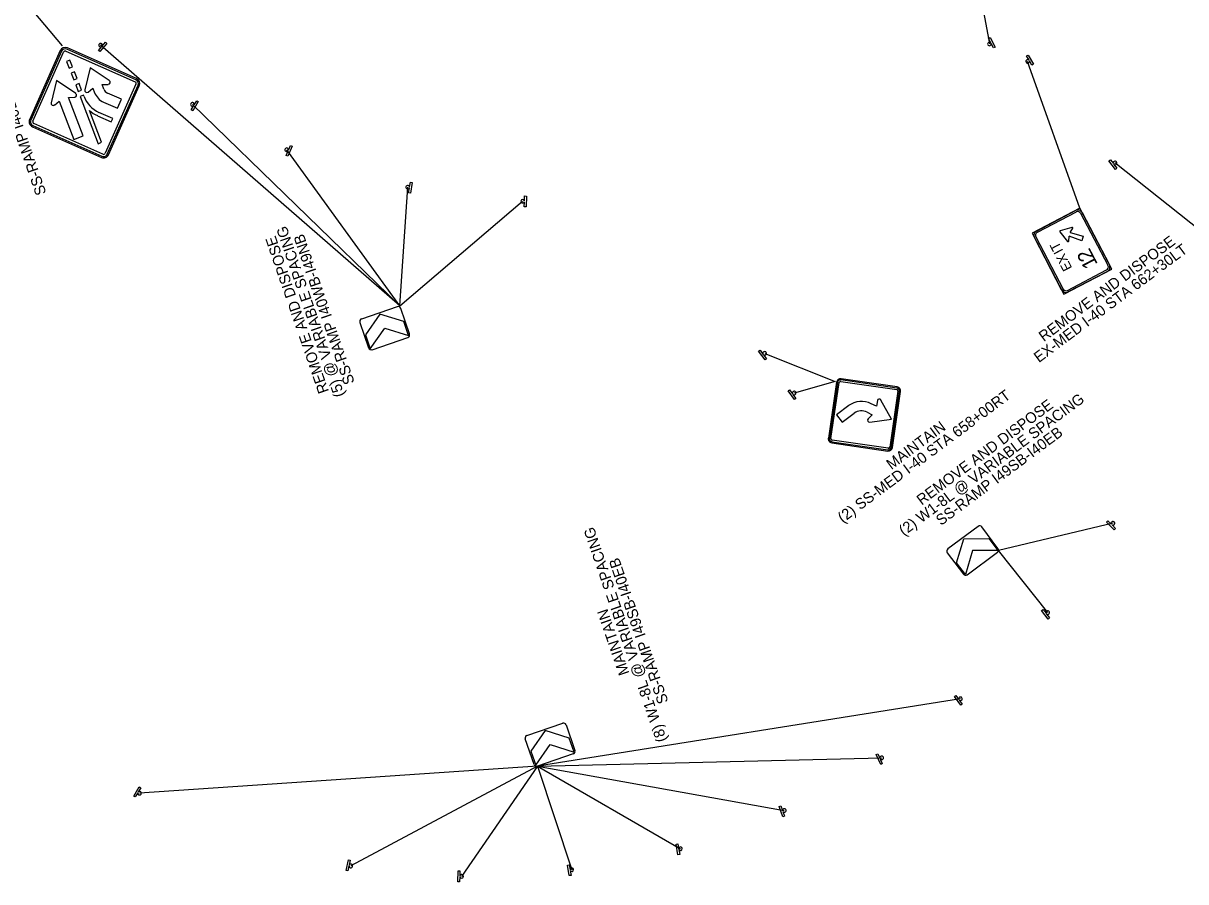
# Model space of a CAD drawing. Extents: x 641128 to 649424, y 422807 to 432853.
# Drawn here: x 644900 to 646193, y 425986 to 426941 of the extents above; entities that cross this region are included whole.
import ezdxf

# ---------------------------------------------------------------- set-up
doc = ezdxf.new("R2010")
doc.units = 0
for name, color, linetype in [('R_Anno_Text', 7, 'Continuous'), ('R_Dimension_2', 7, 'Continuous'), ('S_SIGN', 7, 'Continuous')]:
    doc.layers.add(name, color=color, linetype=linetype)

msp = doc.modelspace()

# ---------------------------------------------------------------- linework, layer by layer
at = {"layer": 'S_SIGN'}
for p, q in [((645890, 427374.3), (645974.6, 426917.5)), ((644944, 426915.5), (644741.6, 427157.1)), ((644988.1, 426915.2), (644991.7, 426919.4)), ((644991.7, 426919.4), (644993.2, 426918.1)), ((645973.6, 426923.7), (645975.4, 426924.6)), ((645976.2, 426918.8), (645973.6, 426923.7)), ((645975.4, 426924.6), (645981, 426914)), ((644941.5, 426910.1), (644907.4, 426833.3)), ((645026.2, 426879), (644949.4, 426913.1)), ((644983.8, 426910.3), (644987.5, 426914.5)), ((644985.3, 426909), (644983.8, 426910.3)), ((644993.2, 426918.1), (644985.3, 426909)), ((645319, 426626.2), (644986.3, 426916.2)), ((644987.5, 426914.5), (644987.4, 426914.6)), ((644988, 426915.3), (644988.1, 426915.2)), ((645976.1, 426918.8), (645976.2, 426918.8)), ((645979.2, 426913.1), (645976.6, 426918)), ((645976.6, 426918), (645976.6, 426918)), ((645981, 426914), (645979.2, 426913.1)), ((646015.8, 426904.2), (646017.5, 426905.2)), ((646018.6, 426899.4), (646015.8, 426904.2)), ((646075.2, 426734.7), (646017.1, 426898)), ((646017.5, 426905.2), (646023.7, 426894.9)), ((646018.6, 426899.4), (646018.6, 426899.4)), ((646019.1, 426898.6), (646019, 426898.6)), ((646021.9, 426893.9), (646019.1, 426898.6)), ((646023.7, 426894.9), (646021.9, 426893.9)), ((644974.8, 426891.1), (644968.7, 426866.3)), ((644995.9, 426876.8), (644974.8, 426891.1)), ((644937.4, 426876.7), (644931.3, 426851.9)), ((644958.6, 426862.4), (644937.4, 426876.7)), ((644972.3, 426864), (644977.6, 426868.3)), ((644977.6, 426868.3), (644979.6, 426863.3)), ((644987.9, 426872.3), (644994.8, 426872.6)), ((644989.8, 426867.3), (644987.9, 426872.3)), ((644995.1, 426794.3), (645029.2, 426871)), ((644950.6, 426857.9), (644957.5, 426858.3)), ((644967, 426815.2), (644950.6, 426857.9)), ((644967.3, 426860.4), (644963.6, 426858.9)), ((644963.6, 426858.9), (644983.7, 426806.6)), ((644967.9, 426858.9), (644967.3, 426860.4)), ((645009.4, 426856), (644994, 426862.8)), ((645004.9, 426846), (645009.4, 426856)), ((645090.4, 426849.7), (645093.2, 426854.4)), ((645093.2, 426854.4), (645094.9, 426853.4)), ((644934.9, 426849.6), (644940.3, 426854)), ((644940.3, 426854), (644956.7, 426811.3)), ((644987.4, 426808.1), (644973.8, 426843.6)), ((644999.8, 426834.6), (644984.5, 426841.4)), ((644989.6, 426852.8), (645004.9, 426846)), ((645087, 426844.1), (645089.9, 426848.9)), ((645088.7, 426843.1), (645087, 426844.1)), ((645319, 426626.2), (645088.4, 426850.3)), ((645094.9, 426853.4), (645088.7, 426843.1)), ((645089.9, 426848.9), (645089.9, 426848.9)), ((645090.3, 426849.7), (645090.4, 426849.7)), ((644982.9, 426837.7), (644998.2, 426830.9)), ((644998.2, 426830.9), (644999.8, 426834.6)), ((644910.4, 426825.4), (644987.2, 426791.2)), ((644956.7, 426811.3), (644967, 426815.2)), ((644983.7, 426806.6), (644987.4, 426808.1)), ((645199.2, 426803.8), (645194.5, 426792.7)), ((645195.2, 426799.5), (645197.3, 426804.6)), ((645197.3, 426804.6), (645199.2, 426803.8)), ((645192.7, 426793.5), (645194.8, 426798.6)), ((645194.5, 426792.7), (645192.7, 426793.5)), ((645319, 426626.2), (645193.2, 426799.8)), ((645194.8, 426798.6), (645194.8, 426798.7)), ((645195.1, 426799.5), (645195.2, 426799.5)), ((646107.5, 426787.6), (646109.1, 426788.8)), ((646114.6, 426778), (646107.5, 426787.6)), ((646109.1, 426788.8), (646112.4, 426784.4)), ((646112.4, 426784.4), (646112.4, 426784.4)), ((646113, 426783.7), (646112.9, 426783.6)), ((646112.9, 426783.6), (646116.2, 426779.2)), ((646343.9, 426602.6), (646114.2, 426785.2)), ((646116.2, 426779.2), (646114.6, 426778)), ((645329.9, 426758.3), (645330.9, 426763.8)), ((645330.9, 426763.8), (645332.8, 426763.4)), ((645319, 426626.2), (645327.8, 426758.2)), ((645328.7, 426752), (645329.7, 426757.4)), ((645330.7, 426751.6), (645328.7, 426752)), ((645329.7, 426757.4), (645329.7, 426757.5)), ((645329.8, 426758.3), (645329.9, 426758.3)), ((645332.8, 426763.4), (645330.7, 426751.6)), ((645319, 426626.2), (645455.5, 426742.6)), ((645457.3, 426736.5), (645457.5, 426742)), ((645457.5, 426742.9), (645457.8, 426748.5)), ((645457.5, 426742.9), (645457.5, 426742.9)), ((645457.5, 426742), (645457.5, 426742)), ((645457.8, 426748.5), (645459.8, 426748.4)), ((645459.8, 426748.4), (645459.3, 426736.4)), ((645459.3, 426736.4), (645457.3, 426736.5)), ((645316.2, 426625.2), (645276.5, 426611.6)), ((645329.7, 426595), (645320, 426623.4)), ((645296.8, 426617), (645280.9, 426594.1)), ((645323.4, 426608.7), (645296.8, 426617)), ((645274.6, 426607.8), (645284.3, 426579.4)), ((645286.2, 426578.5), (645302.2, 426601.4)), ((645302.2, 426601.4), (645328.8, 426593.1)), ((645288.2, 426577.5), (645327.9, 426591.2)), ((645717.9, 426575.7), (645719.5, 426576.9)), ((645725.1, 426566.1), (645717.9, 426575.7)), ((645719.5, 426576.9), (645722.8, 426572.4)), ((645722.8, 426572.4), (645722.9, 426572.4)), ((645723.4, 426571.7), (645723.4, 426571.7)), ((645723.4, 426571.7), (645726.7, 426567.3)), ((645726.7, 426567.3), (645725.1, 426566.1)), ((645872, 426536), (645809.7, 426545.1)), ((645750.7, 426531.7), (645752.3, 426532.9)), ((645757.8, 426522.1), (645750.7, 426531.7)), ((645752.3, 426532.9), (645755.6, 426528.5)), ((645804.6, 426541.3), (645795.5, 426479)), ((645755.6, 426528.5), (645755.6, 426528.5)), ((645756.2, 426527.8), (645756.1, 426527.7)), ((645756.1, 426527.7), (645759.4, 426523.3)), ((645759.4, 426523.3), (645757.8, 426522.1)), ((645850, 426520.8), (645849, 426514.5)), ((645865.7, 426500.2), (645854, 426521.5)), ((645866.7, 426468.6), (645875.8, 426530.9)), ((645818.1, 426515.3), (645804.6, 426505.2)), ((645810.9, 426496.8), (645824.3, 426506.8)), ((645838.5, 426508.1), (645844.3, 426505.1)), ((645849, 426514.5), (645843.2, 426517.4)), ((645804.6, 426505.2), (645810.9, 426496.8)), ((645844.3, 426505.1), (645839.8, 426500.6)), ((645841.6, 426497), (645865.7, 426500.2)), ((645799.3, 426473.9), (645861.6, 426464.8)), ((645962, 426381), (645928.3, 426355.9)), ((645984.1, 426356.4), (645966.2, 426380.4)), ((646112, 426384.4), (645984.7, 426354)), ((646104.9, 426385.8), (646106.4, 426387.2)), ((646113.4, 426377.3), (646104.9, 426385.8)), ((646106.4, 426387.2), (646110.3, 426383.3)), ((646110.3, 426383.3), (646110.3, 426383.3)), ((646111, 426382.7), (646110.9, 426382.6)), ((646110.9, 426382.6), (646114.8, 426378.7)), ((646114.8, 426378.7), (646113.4, 426377.3)), ((645937.9, 426340.6), (645946.1, 426367.3)), ((645946.1, 426367.3), (645974, 426367.5)), ((645927.7, 426351.7), (645945.7, 426327.7)), ((645955.9, 426354.1), (645947.8, 426327.4)), ((645949.8, 426327.1), (645983.5, 426352.2)), ((645983.8, 426354.3), (645955.9, 426354.1)), ((646039.4, 426285.1), (645984.7, 426354)), ((646032.6, 426287.5), (646034.2, 426288.7)), ((646039.9, 426277.9), (646032.6, 426287.5)), ((646034.2, 426288.7), (646037.6, 426284.3)), ((646037.6, 426284.3), (646037.6, 426284.3)), ((646038.2, 426283.6), (646038.1, 426283.5)), ((646038.1, 426283.5), (646041.5, 426279.1)), ((646041.5, 426279.1), (646039.9, 426277.9)), ((645942.4, 426189.2), (645472, 426114.3)), ((645935.6, 426191.6), (645937.2, 426192.8)), ((645942.8, 426182), (645935.6, 426191.6)), ((645937.2, 426192.8), (645940.5, 426188.3)), ((645940.5, 426188.3), (645940.6, 426188.4)), ((645941.1, 426187.6), (645941.1, 426187.6)), ((645941.1, 426187.6), (645944.4, 426183.2)), ((645944.4, 426183.2), (645942.8, 426182)), ((645460.3, 426148.4), (645500.1, 426162)), ((645503.9, 426160.2), (645513.6, 426131.8)), ((645468.2, 426116.2), (645458.5, 426144.6)), ((645480.7, 426153.8), (645464.8, 426130.9)), ((645507.3, 426145.5), (645480.7, 426153.8)), ((645470.1, 426115.3), (645486, 426138.2)), ((645486, 426138.2), (645512.7, 426129.9)), ((645511.8, 426128), (645472, 426114.3)), ((645472, 426114.3), (645854.8, 426123.5)), ((645848.7, 426127.3), (645850.5, 426128.1)), ((645853.7, 426116.3), (645848.7, 426127.3)), ((645850.5, 426128.1), (645852.8, 426123)), ((645852.8, 426123), (645852.9, 426123)), ((645853.3, 426122.2), (645853.2, 426122.2)), ((645853.2, 426122.2), (645855.5, 426117.2)), ((645472, 426114.3), (645029.6, 426084.2)), ((645472, 426114.3), (645264.5, 426003.3)), ((645472, 426114.3), (645387.7, 425991.7)), ((645472, 426114.3), (645510.3, 425999.1)), ((645472, 426114.3), (645631.1, 426022.4)), ((645472, 426114.3), (645746.5, 426065)), ((645855.5, 426117.2), (645853.7, 426116.3)), ((645023.1, 426081.1), (645029.3, 426091.4)), ((645024.8, 426080), (645023.1, 426081.1)), ((645027.6, 426084.8), (645024.8, 426080)), ((645027.7, 426084.8), (645027.6, 426084.8)), ((645031, 426090.3), (645028.1, 426085.6)), ((645028.1, 426085.6), (645028.1, 426085.5)), ((645029.3, 426091.4), (645031, 426090.3)), ((645740.8, 426069.4), (645742.7, 426070.1)), ((645744.7, 426058), (645740.8, 426069.4)), ((645742.7, 426070.1), (645744.5, 426064.8)), ((645744.5, 426064.8), (645744.6, 426064.8)), ((645746.6, 426058.7), (645744.7, 426058)), ((645744.9, 426063.9), (645744.8, 426063.9)), ((645744.8, 426063.9), (645746.6, 426058.7)), ((645626.1, 426027.6), (645628.1, 426028)), ((645628.2, 426015.8), (645626.1, 426027.6)), ((645628.1, 426028), (645629, 426022.5)), ((645630.2, 426016.2), (645628.2, 426015.8)), ((645629, 426022.5), (645629.1, 426022.5)), ((645629.3, 426021.6), (645629.2, 426021.6)), ((645629.2, 426021.6), (645630.2, 426016.2)), ((645259.3, 425998.3), (645261.9, 426010)), ((645262.4, 426003.3), (645261.2, 425997.9)), ((645261.9, 426010), (645263.9, 426009.6)), ((645262.5, 426003.3), (645262.4, 426003.3)), ((645263.9, 426009.6), (645262.6, 426004.2)), ((645262.6, 426004.2), (645262.7, 426004.2)), ((645505.3, 426004.3), (645507.3, 426004.6)), ((645507.4, 425992.5), (645505.3, 426004.3)), ((645507.3, 426004.6), (645508.3, 425999.1)), ((645261.2, 425997.9), (645259.3, 425998.3)), ((645383.5, 425985.8), (645383.8, 425997.8)), ((645383.8, 425997.8), (645385.8, 425997.7)), ((645385.6, 425991.2), (645385.5, 425985.7)), ((645385.7, 425991.2), (645385.6, 425991.2)), ((645385.8, 425997.7), (645385.7, 425992.2)), ((645385.7, 425992.2), (645385.7, 425992.1)), ((645509.4, 425992.8), (645507.4, 425992.5)), ((645508.3, 425999.1), (645508.3, 425999.1)), ((645508.5, 425998.3), (645508.4, 425998.2)), ((645508.4, 425998.2), (645509.4, 425992.8)), ((645385.5, 425985.7), (645383.5, 425985.8))]:
    msp.add_line(p, q, dxfattribs=at)
for points in [[(644942.9, 426909.4), (644908.8, 426832.7)], [(644911, 426831.7), (644945.2, 426908.4)], [(644942.9, 426909.4), (644942.9, 426909.4), (644942.9, 426909.4)], [(644947.8, 426909.4), (645024.6, 426875.3)], [(645025.6, 426877.6), (644948.8, 426911.7)], [(644952.2, 426899.6), (644948.5, 426898.1), (644951.4, 426890.7), (644955.1, 426892.1), (644952.2, 426899.6)], [(644957.3, 426886.5), (644953.5, 426885.1), (644956.4, 426877.6), (644960.1, 426879), (644957.3, 426886.5)], [(644962.3, 426873.4), (644958.6, 426872), (644961.4, 426864.5), (644965.2, 426866), (644962.3, 426873.4)], [(645025.6, 426872.7), (644991.4, 426795.9)], [(644993.7, 426794.9), (645027.9, 426871.7)], [(645025.6, 426877.6), (645025.6, 426877.6), (645025.6, 426877.6)], [(644988.8, 426794.9), (644912.1, 426829)], [(644911, 426826.8), (644987.8, 426792.6)], [(644911, 426826.8), (644911, 426826.8), (644911, 426826.8)], [(644993.7, 426794.9), (644993.7, 426794.9), (644993.7, 426794.9)], [(646110.6, 426667.1), (646075.2, 426734.7), (646022, 426706.9), (646057.5, 426639.2), (646110.6, 426667.1), (646110.6, 426667.1), (646110.6, 426667.1)], [(646026.9, 426709.4), (646070.4, 426732.2)], [(646071.2, 426730.6), (646027.7, 426707.8)], [(646071.2, 426730.6), (646071.2, 426730.6), (646071.2, 426730.6)], [(646106.5, 426671.1), (646076.1, 426729.1)], [(646077.7, 426729.9), (646108.1, 426671.9)], [(646066.4, 426713.5), (646053.3, 426709.7)], [(646064.3, 426707.8), (646067.2, 426712.5)], [(646054.9, 426644.1), (646024.6, 426702.1)], [(646026.2, 426702.9), (646056.5, 426644.9)], [(646026.2, 426702.9), (646026.2, 426702.9), (646026.2, 426702.9)], [(646053, 426708.6), (646061.5, 426697.9)], [(646053.5, 426709), (646053.5, 426709), (646053.5, 426709)], [(646062.7, 426698.3), (646063.1, 426703.9)], [(646079, 426703.9), (646077.4, 426698.7), (646063.1, 426703.9)], [(646064.3, 426707.8), (646079, 426703.9), (646079, 426703.9), (646079, 426703.9)], [(646061.4, 426643.4), (646104.9, 426666.2)], [(646105.8, 426664.5), (646062.3, 426641.8)], [(646106.5, 426671.1), (646106.5, 426671.1), (646106.5, 426671.1)], [(646061.4, 426643.4), (646061.4, 426643.4), (646061.4, 426643.4)], [(645280.9, 426594.1), (645286.2, 426578.5), (645302.2, 426601.4), (645328.8, 426593.1), (645323.4, 426608.7), (645296.8, 426617), (645280.9, 426594.1)], [(645724.7, 426573.3), (645803.2, 426542.1), (645757.5, 426529.3)], [(645805.8, 426541.2), (645796.7, 426478.8)], [(645798.4, 426478.6), (645807.6, 426540.9)], [(645805.8, 426541.2), (645805.8, 426541.2), (645805.8, 426541.2)], [(645809.3, 426542.2), (645871.6, 426533.1)], [(645871.8, 426534.8), (645809.5, 426543.9)], [(645872.9, 426531.4), (645863.8, 426469)], [(645865.5, 426468.8), (645874.6, 426531.1)], [(645871.8, 426534.8), (645871.8, 426534.8), (645871.8, 426534.8)], [(645799.5, 426475.1), (645861.8, 426466)], [(645799.5, 426475.1), (645799.5, 426475.1), (645799.5, 426475.1)], [(645862.1, 426467.8), (645799.7, 426476.9)], [(645865.5, 426468.8), (645865.5, 426468.8), (645865.5, 426468.8)], [(645974, 426367.5), (645983.8, 426354.3), (645955.9, 426354.1), (645947.8, 426327.4), (645937.9, 426340.6), (645946.1, 426367.3), (645974, 426367.5)], [(645464.8, 426130.9), (645470.1, 426115.3), (645486, 426138.2), (645512.7, 426129.9), (645507.3, 426145.5), (645480.7, 426153.8), (645464.8, 426130.9)]]:
    msp.add_lwpolyline(points, dxfattribs=at)
for centre, radius, start, end in [((645974.6, 426917.5), 2, 117.5985, 15.2786), ((645974.6, 426917.5), 2, 41.4606, 117.5985), ((644947, 426907.6), 6, 66.0231, 156.0228), ((644947, 426907.6), 4.5, 66.0231, 156.0228), ((644947, 426907.6), 2, 66.0231, 156.0228), ((644986.3, 426916.2), 2, 48.9305, 306.6106), ((644986.3, 426916.2), 2, 332.7926, 48.9305), ((646017.1, 426898), 2, 120.9595, 18.6396), ((646017.1, 426898), 2, 44.8216, 120.9595), ((644997.3, 426870.2), 8, 201.0229, 246.023), ((644994.7, 426874.9), 2.25, 273.1388, 55.8707), ((645023.8, 426873.5), 2, 336.0233, 66.0229), ((645023.8, 426873.5), 4.5, 336.0233, 66.0229), ((645023.8, 426873.5), 6, 336.0233, 66.0229), ((644957.3, 426860.5), 2.25, 273.1388, 55.8707), ((644997.3, 426870.2), 31.5, 201.0229, 246.023), ((644970.9, 426865.7), 2.25, 166.1756, 308.9075), ((644997.3, 426870.2), 19, 201.0229, 246.023), ((644933.5, 426851.4), 2.25, 166.1756, 308.9075), ((644997.3, 426870.2), 35.5, 228.4842, 246.023), ((645088.4, 426850.3), 2, 58.8255, 316.5056), ((645088.4, 426850.3), 2, 342.6877, 58.8255), ((644912.9, 426830.9), 6, 156.0228, 246.023), ((644912.9, 426830.9), 4.5, 156.0228, 246.023), ((644912.9, 426830.9), 2, 156.0228, 246.023), ((644989.6, 426796.7), 6, 246.023, 336.0233), ((644989.6, 426796.7), 4.5, 246.023, 336.0233), ((644989.6, 426796.7), 2, 246.023, 336.0233), ((645193.2, 426799.8), 2, 67.1027, 324.7828), ((645193.2, 426799.8), 2, 350.9648, 67.1027), ((646114.2, 426785.2), 2, 306.6766, 204.3567), ((646114.2, 426785.2), 2, 230.5387, 306.6766), ((645327.8, 426758.2), 2, 79.8014, 337.4815), ((645327.8, 426758.2), 2, 3.6635, 79.8014), ((645455.5, 426742.6), 2, 87.6025, 345.2826), ((645455.5, 426742.6), 2, 11.4646, 87.6025), ((646072.9, 426727.4), 5.45, 27.629, 117.6292), ((646072.9, 426727.4), 3.64, 27.629, 117.6292), ((646066.6, 426712.9), 0.682, 328.6671, 106.4508), ((646029.4, 426704.6), 5.45, 117.6289, 207.6291), ((646029.4, 426704.6), 3.64, 117.6289, 207.6291), ((646053.5, 426709), 0.682, 106.4508, 218.8067), ((646062.1, 426698.3), 0.682, 218.807, 356.5913), ((646103.2, 426669.4), 3.64, 297.6288, 27.629), ((646103.2, 426669.4), 5.45, 297.6288, 27.629), ((646059.8, 426646.6), 5.45, 207.6291, 297.6288), ((646059.8, 426646.6), 3.64, 207.6291, 297.6288), ((645317.2, 426622.4), 3, 18.9552, 108.9554), ((645277.4, 426608.8), 3, 108.9552, 198.9554), ((645326.9, 426594), 3, 288.955, 18.9552), ((645287.2, 426580.4), 3, 198.9554, 288.955), ((645724.7, 426573.3), 2, 306.4828, 204.1629), ((645724.7, 426573.3), 2, 230.345, 306.4828), ((645809, 426540.7), 4.5, 81.69, 171.6902), ((645757.5, 426529.3), 2, 306.4828, 204.1629), ((645809, 426540.7), 3.25, 81.69, 171.6902), ((645809, 426540.7), 1.5, 81.69, 171.6902), ((645871.4, 426531.6), 1.5, 351.6902, 81.69), ((645871.4, 426531.6), 3.25, 351.6902, 81.69), ((645871.4, 426531.6), 4.5, 351.6902, 81.69), ((645757.5, 426529.3), 2, 230.345, 306.4828), ((645832.4, 426496), 24, 63.2459, 126.6901), ((645852.1, 426520.5), 2.13, 28.7945, 171.0737), ((645832.4, 426496), 13.5, 63.2459, 126.6901), ((645841.3, 426499.1), 2.13, 135.418, 277.6971), ((645799.9, 426478.4), 4.5, 171.6902, 261.6904), ((645799.9, 426478.4), 3.25, 171.6902, 261.6904), ((645799.9, 426478.4), 1.5, 171.6902, 261.6904), ((645862.3, 426469.2), 4.5, 261.6904, 351.6901), ((645862.3, 426469.2), 3.25, 261.6904, 351.6901), ((645862.3, 426469.2), 1.5, 261.6904, 351.6901), ((645963.8, 426378.6), 3, 36.6905, 126.6901), ((646112, 426384.4), 2, 314.5285, 212.2086), ((646112, 426384.4), 2, 238.3906, 314.5285), ((645930.1, 426353.5), 3, 126.6901, 216.6903), ((645981.7, 426354.6), 3, 306.6902, 36.6905), ((645948.1, 426329.5), 3, 216.6903, 306.6905), ((646039.4, 426285.1), 2, 307.2028, 204.8829), ((646039.4, 426285.1), 2, 231.0649, 307.2028), ((645942.4, 426189.2), 2, 307.2028, 204.8829), ((645942.4, 426189.2), 2, 231.0649, 307.2028), ((645501, 426159.2), 3, 18.9551, 108.9553), ((645461.3, 426145.6), 3, 108.9553, 198.955), ((645510.8, 426130.8), 3, 288.9549, 18.9551), ((645854.8, 426123.5), 2, 294.4707, 192.1508), ((645854.8, 426123.5), 2, 218.3328, 294.4707), ((645471.1, 426117.2), 3, 198.955, 288.9552), ((645029.6, 426084.2), 2, 162.944, 239.0818), ((645029.6, 426084.2), 2, 239.0818, 136.7619), ((645746.5, 426065), 2, 288.6171, 186.2972), ((645746.5, 426065), 2, 212.4792, 288.6171), ((645631.1, 426022.4), 2, 280.1227, 177.8028), ((645631.1, 426022.4), 2, 203.9849, 280.1227), ((645264.5, 426003.3), 2, 181.0044, 257.1422), ((645264.5, 426003.3), 2, 257.1422, 154.8223), ((645387.7, 425991.7), 2, 268.6907, 166.3708), ((645387.7, 425991.7), 2, 192.5528, 268.6907), ((645510.3, 425999.1), 2, 280.1227, 177.8028), ((645510.3, 425999.1), 2, 203.9849, 280.1227)]:
    msp.add_arc(centre, radius, start, end, dxfattribs=at)

# ---------------------------------------------------------------- texts
at = {"layer": 'R_Anno_Text'}
for s, p in [('REMOVE AND DISPOSE', (646035.1, 426585.8)), ('EX-MED I-40 STA 662+30LT', (646029.6, 426562.5)), ('(2) SS-MED I-40 STA 658+00RT', (645811.5, 426384.3)), ('(2) W1-8L @ VARIABLE SPACING', (645879.5, 426369.9)), ('REMOVE AND DISPOSE', (645899.3, 426403.9)), ('MAINTAIN', (645865.6, 426443.5)), ('SS-RAMP I49SB-I40EB', (645920.7, 426381.3))]:
    msp.add_text(s, height=12, rotation=36.6902, dxfattribs=at).set_placement(p)
at = {"layer": 'R_Dimension_2'}
for s, p in [('SS-RAMP I40EB-I49NB STA 138+59RT', (644926.1, 426751.6)), ('(5) @ VARIABLE SPACING', (645257.7, 426527)), ('REMOVE AND DISPOSE ', (645240.3, 426531.2)), ('SS-RAMP I40WB-I49NB', (645268.9, 426541.1)), ('(8) W1-8L @ VARIABLE SPACING', (645616.2, 426143.3)), ('SS-RAMP I49SB-I40EB', (645617.8, 426186)), ('MAINTAIN', (645574.4, 426217.7))]:
    msp.add_text(s, height=12, rotation=108.9552, dxfattribs=at).set_placement(p)
at = {"layer": 'S_SIGN'}
for s, height, p in [('T', 10.9, (646055, 426690.9)), ('I', 10.9, (646056.9, 426687.3)), ('2', 16.4, (646091.2, 426680.7)), ('X', 10.9, (646062.4, 426676.8)), ('E', 10.9, (646066.9, 426668.3)), ('1', 16.4, (646095.4, 426672.7))]:
    msp.add_text(s, height=height, rotation=117.6289, dxfattribs=at).set_placement(p)

doc.saveas('drawing.dxf')
